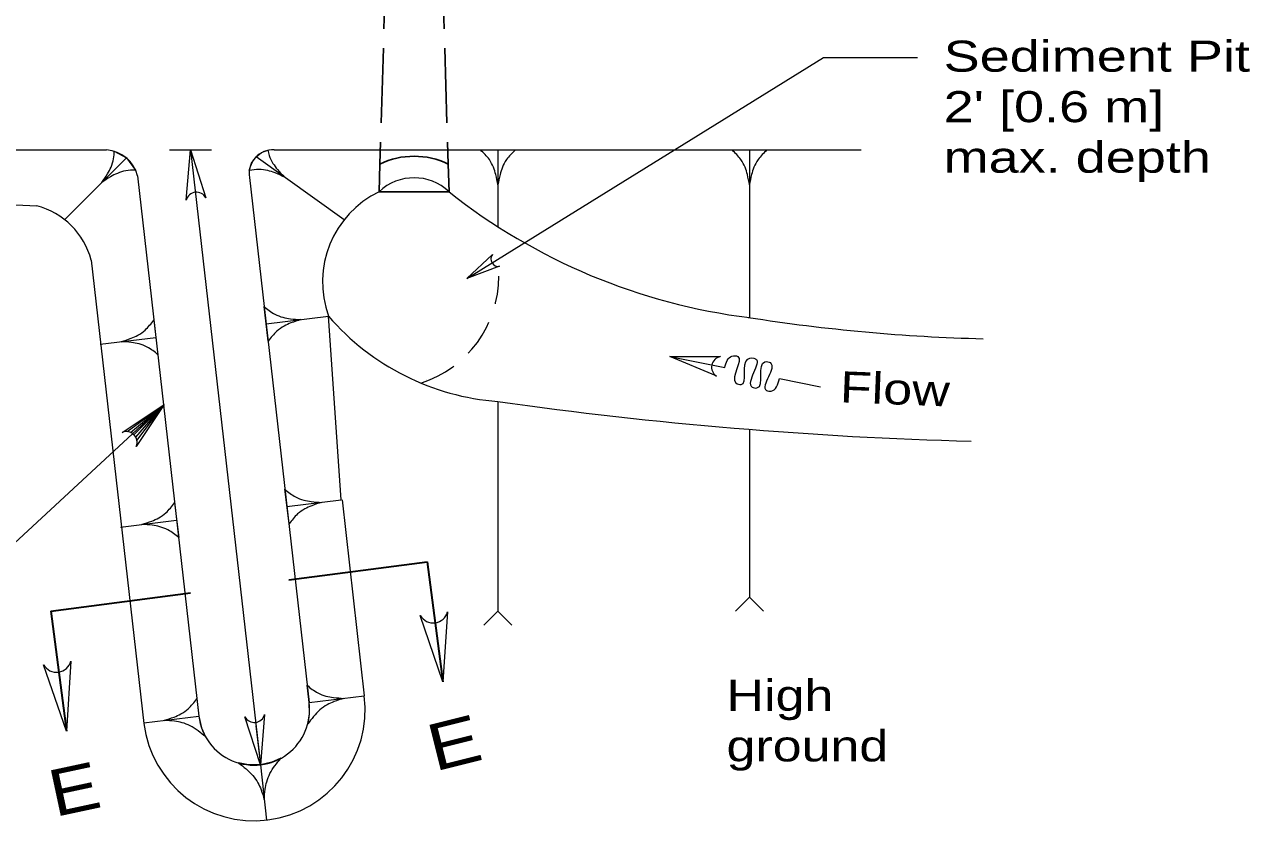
# Model space of a CAD drawing. Extents: x 1043.1 to 1101.1, y 672.4 to 716.4.
# Drawn here: x 1050.72 to 1057.03, y 684.13 to 688.26 of the extents above; entities that cross this region are included whole.
import ezdxf
from ezdxf.enums import TextEntityAlignment as Align

# ---------------------------------------------------------------- set-up
doc = ezdxf.new("R2010")
doc.units = 0
doc.header["$LTSCALE"] = 0.064
doc.linetypes.add('LONG_DASHED', pattern=[7.5, 6, -1.5])
doc.linetypes.add('MEDIUM_DASHED', pattern=[4.5, 3, -1.5])
doc.layers.add('1', color=7, linetype='Continuous', lineweight=13)

msp = doc.modelspace()

# ---------------------------------------------------------------- linework, layer by layer
at = {"layer": '1', "linetype": 'LONG_DASHED', "lineweight": 25}
for p, q in [((1052.58533, 688.62467), (1052.55375, 687.54417)), ((1052.87325, 688.62467), (1052.905, 687.54417))]:
    msp.add_line(p, q, dxfattribs=at)
at = {"layer": '1'}
for p, q in [((1047.11617, 687.61725), (1051.14617, 687.61725)), ((1051.24892, 687.57625), (1050.92983, 687.25717)), ((1051.46992, 687.61725), (1051.68583, 687.61725)), ((1052.3695, 687.2575), (1051.916, 687.58142)), ((1052.00975, 687.61725), (1055.03217, 687.61725)), ((1053.07117, 687.61725), (1053.25117, 687.61725)), ((1053.07117, 687.61725), (1053.25117, 687.61725)), ((1053.16117, 687.61725), (1053.16117, 687.2215)), ((1054.3665, 687.61725), (1054.54642, 687.61725)), ((1054.4565, 687.61725), (1054.4565, 686.75392)), ((1051.30533, 687.48342), (1051.62133, 684.702)), ((1051.88192, 687.47517), (1052.18917, 684.77167)), ((1051.06675, 687.049), (1051.33783, 684.66425)), ((1051.9785, 686.63208), (1051.95675, 686.81067)), ((1051.9785, 686.63208), (1051.95675, 686.81067)), ((1051.38883, 686.74092), (1051.41075, 686.5625)), ((1051.96767, 686.72142), (1052.28892, 686.76092)), ((1052.354, 685.81492), (1052.28892, 686.76092)), ((1051.11233, 686.61642), (1051.39975, 686.65167)), ((1054.0465, 686.553), (1054.32875, 686.49625)), ((1054.61092, 686.43942), (1054.82267, 686.39692)), ((1051.25233, 686.16692), (1051.44233, 686.307)), ((1051.26917, 686.1625), (1051.44233, 686.307)), ((1051.28675, 686.15075), (1051.44233, 686.307)), ((1051.2965, 686.13758), (1051.44233, 686.307)), ((1051.30233, 686.12075), (1051.44233, 686.307)), ((1053.16117, 686.32208), (1053.16117, 685.24267)), ((1054.4565, 686.17825), (1054.4565, 685.31467)), ((1052.08542, 685.69125), (1052.06367, 685.86967)), ((1051.49575, 685.80008), (1051.51767, 685.62158)), ((1052.0745, 685.78058), (1052.354, 685.81492)), ((1052.35842, 685.81542), (1052.473, 684.8065)), ((1051.21842, 685.6755), (1051.50675, 685.71092)), ((1053.16117, 685.24267), (1053.08917, 685.17092)), ((1053.16117, 685.24267), (1053.23317, 685.17092)), ((1052.18917, 684.77167), (1052.473, 684.8065)), ((1051.3375, 684.66708), (1051.62133, 684.702)), ((1051.91492, 684.65217), (1051.93775, 684.45117))]:
    msp.add_line(p, q, dxfattribs=at)
at = {"layer": '1', "lineweight": 25}
for p, q in [((1052.5495, 687.4015), (1052.55375, 687.54417)), ((1052.90925, 687.4015), (1052.905, 687.54417)), ((1052.5495, 687.4015), (1052.90925, 687.4015)), ((1054.4565, 685.31467), (1054.3845, 685.24267)), ((1054.4565, 685.31467), (1054.52842, 685.24267))]:
    msp.add_line(p, q, dxfattribs=at)
at = {"layer": '1', "lineweight": 35}
for p, q in [((1052.08475, 685.40317), (1052.79642, 685.49617)), ((1052.79642, 685.49617), (1052.87725, 684.87842)), ((1050.85833, 685.24267), (1051.57775, 685.33675)), ((1050.85833, 685.24267), (1050.93917, 684.625))]:
    msp.add_line(p, q, dxfattribs=at)
at = {"layer": '1'}
for points in [[(1053.00092, 686.95475), (1054.83842, 688.09183), (1055.32175, 688.09183)], [(1051.18533, 687.61), (1051.24875, 687.57625), (1051.29433, 687.51267)], [(1051.55617, 687.35892), (1051.57792, 687.61725), (1051.65717, 687.3705), (1051.65692, 687.3705)], [(1051.57792, 687.61725), (1051.93775, 684.45117), (1051.97, 684.16717)], [(1051.8805, 687.51025), (1051.89275, 687.5495), (1051.91567, 687.582), (1051.94417, 687.6035), (1051.97692, 687.61492)], [(1047.11617, 687.3295), (1049.275, 687.4015), (1050.78633, 687.3295)], [(1053.16958, 687.01767), (1053.00092, 686.95475), (1053.13242, 687.07767), (1053.13242, 687.07758)], [(1054.28575, 686.45308), (1054.0465, 686.553), (1054.30583, 686.55275), (1054.30583, 686.5525)], [(1051.44233, 686.307), (1049.68783, 684.68225), (1049.16592, 684.68225)], [(1051.22633, 686.16242), (1051.44233, 686.307), (1051.29867, 686.0905)], [(1052.90175, 685.23858), (1052.87725, 684.87842), (1052.76142, 685.22033), (1052.7615, 685.22025)], [(1050.96208, 684.98525), (1050.93917, 684.625), (1050.82183, 684.96642), (1050.82192, 684.96633)], [(1052.18192, 684.66158), (1052.19075, 684.7145), (1052.18925, 684.77142), (1052.17825, 684.86092)], [(1051.61025, 684.79125), (1051.62117, 684.702), (1051.63417, 684.642), (1051.65575, 684.59508)], [(1051.9595, 684.70958), (1051.93775, 684.45117), (1051.8585, 684.69817), (1051.85867, 684.69817)], [(1052.0435, 684.48492), (1051.99767, 684.465), (1051.93883, 684.45125), (1051.87642, 684.45067), (1051.82533, 684.46075)]]:
    msp.add_lwpolyline(points, dxfattribs=at)
for centre, radius, start, end in [((1051.60884, 687.34417), 0.05488, 28.57163, 164.39776), ((1053.16322, 687.05515), 0.03811, 143.83798, 279.6641), ((1054.31604, 686.49869), 0.05488, 100.72224, 236.54837), ((1051.248, 686.11185), 0.05501, 337.19963, 113.02576), ((1052.82795, 685.25788), 0.0764, 209.50449, 345.33062), ((1050.88819, 685.00424), 0.0764, 209.75778, 345.5839), ((1051.90682, 684.72442), 0.05488, 208.57163, 344.39776)]:
    msp.add_arc(centre, radius, start, end, dxfattribs=at)
for centre, major_axis, start_param, end_param in [((1051.13154, 687.43849), (0.17947, 0), 0.2528676, 1.4893571), ((1052.00303, 687.4949), (0.12264, 0), 1.5162862, 3.3026684), ((1052.72935, 687.21259), (-0.26087, 0), 3.9513762, 5.4734017), ((1052.77343, 686.93713), (-0.51559, 0), 5.1617951, 6.6322278), ((1054.83633, 689.83284), (-3.10264, 0), 0.9006444, 1.4480657), ((1050.68585, 686.94871), (0.39387, 0), 0.2574972, 1.3128716), ((1053.25603, 687.59696), (-1.27849, 0), 0.7129535, 1.4965093), ((1055.88909, 695.87482), (-9.23372, 0), 1.4142788, 1.5459847), ((1056.16614, 707.46378), (-21.35636, 0), 1.4296205, 1.5442012), ((1051.90542, 684.73547), (-0.57205, 0), 0.1246434, 3.2660493), ((1051.90542, 684.73542), (-0.28603, 0), 0.1170532, 3.2687764)]:
    msp.add_ellipse(centre, major_axis=major_axis, ratio=0.999895, start_param=start_param, end_param=end_param, dxfattribs=at)
at = {"layer": '1', "lineweight": 25}
for centre, major_axis, ratio, start_param, end_param in [((1052.72935, 687.18035), (-0.40408, 0), 0.999895, 4.2625178, 5.1622602), ((1052.83136, 686.96122), (0.56619, 0.11263), 0.904707, 4.4638988, 4.4648781)]:
    msp.add_ellipse(centre, major_axis=major_axis, ratio=ratio, start_param=start_param, end_param=end_param, dxfattribs=at)
at = {"layer": '1', "linetype": 'MEDIUM_DASHED'}
msp.add_ellipse((1052.59129, 686.96443), major_axis=(0.57422, 0), ratio=0.999895, start_param=5.0183817, end_param=6.2872017, dxfattribs=at)
at = {"layer": '1'}
for points in [[(1051.12167, 687.44892), (1051.151, 687.49358), (1051.169, 687.52867), (1051.18192, 687.57175), (1051.18533, 687.61008)], [(1051.97692, 687.61492), (1051.98275, 687.588), (1052.00267, 687.54767), (1052.02617, 687.516), (1052.0625, 687.47675)], [(1053.16117, 687.43742), (1053.15033, 687.48967), (1053.13825, 687.52725), (1053.11692, 687.56692), (1053.07117, 687.61725)], [(1053.16117, 687.43742), (1053.15033, 687.48967), (1053.13825, 687.52725), (1053.11692, 687.56692), (1053.07117, 687.61725)], [(1053.25117, 687.61725), (1053.20533, 687.56692), (1053.184, 687.52725), (1053.17192, 687.48967), (1053.16117, 687.43742)], [(1053.25117, 687.61725), (1053.20533, 687.56692), (1053.184, 687.52725), (1053.17192, 687.48967), (1053.16117, 687.43742)], [(1054.4565, 687.43742), (1054.44575, 687.48967), (1054.43367, 687.52725), (1054.41233, 687.56692), (1054.3665, 687.61725)], [(1054.54642, 687.61725), (1054.50075, 687.56692), (1054.47942, 687.52725), (1054.46733, 687.48967), (1054.4565, 687.43742)], [(1051.29433, 687.51267), (1051.2445, 687.50925), (1051.20142, 687.49625), (1051.16625, 687.47825), (1051.12167, 687.44892)], [(1052.0625, 687.47675), (1052.01375, 687.49842), (1051.976, 687.51042), (1051.9315, 687.51608), (1051.8805, 687.51025)], [(1051.95675, 686.81067), (1052.01233, 686.77142), (1052.05425, 686.75508), (1052.093, 686.74767), (1052.14617, 686.74325)], [(1051.95675, 686.81067), (1052.01233, 686.77142), (1052.05425, 686.75508), (1052.093, 686.74767), (1052.14617, 686.74325)], [(1051.22125, 686.62967), (1051.27183, 686.64692), (1051.30767, 686.66342), (1051.34433, 686.68925), (1051.38883, 686.74092)], [(1052.14617, 686.74325), (1052.0955, 686.72617), (1052.05992, 686.70958), (1052.02317, 686.68367), (1051.9785, 686.63208)], [(1052.14617, 686.74325), (1052.0955, 686.72617), (1052.05992, 686.70958), (1052.02317, 686.68367), (1051.9785, 686.63208)], [(1051.41075, 686.5625), (1051.35517, 686.60167), (1051.31325, 686.61808), (1051.2745, 686.6255), (1051.22125, 686.62967)], [(1054.32875, 686.49625), (1054.36583, 686.55575), (1054.396, 686.55367), (1054.387, 686.41725), (1054.4135, 686.40875), (1054.44825, 686.54008), (1054.48783, 686.542), (1054.47083, 686.39558), (1054.49492, 686.39158), (1054.53625, 686.5265), (1054.5635, 686.52167), (1054.544, 686.37908), (1054.568, 686.37525), (1054.61092, 686.43942)], [(1052.06367, 685.86967), (1052.11917, 685.8305), (1052.161, 685.81425), (1052.19983, 685.80692), (1052.25317, 685.8025)], [(1051.32817, 685.68892), (1051.37867, 685.70608), (1051.41442, 685.72258), (1051.45117, 685.7485), (1051.49575, 685.80008)], [(1052.25317, 685.8025), (1052.20242, 685.78542), (1052.16675, 685.76875), (1052.12992, 685.74292), (1052.08542, 685.69125)], [(1051.51767, 685.62158), (1051.46192, 685.66075), (1051.42, 685.67708), (1051.38133, 685.68458), (1051.32817, 685.68892)], [(1052.17825, 684.86092), (1052.23392, 684.82167), (1052.27575, 684.8055), (1052.3145, 684.798), (1052.36775, 684.79358)], [(1051.44275, 684.68008), (1051.49333, 684.69708), (1051.52917, 684.71375), (1051.56583, 684.73967), (1051.61025, 684.79125)], [(1052.36775, 684.79358), (1052.31717, 684.7765), (1052.28142, 684.76), (1052.24475, 684.73408), (1052.18192, 684.66158)], [(1051.65633, 684.59458), (1051.57667, 684.652), (1051.53475, 684.66825), (1051.496, 684.67567), (1051.44275, 684.68008)], [(1051.958, 684.2725), (1051.96283, 684.32567), (1051.97075, 684.36425), (1051.98733, 684.40608), (1052.0435, 684.48492)], [(1051.82533, 684.46075), (1051.8995, 684.39608), (1051.92517, 684.35917), (1051.94142, 684.32325), (1051.958, 684.2725)]]:
    msp.add_spline(points, degree=3, dxfattribs=at)

# ---------------------------------------------------------------- texts
for s, width, p in [('Sediment Pit', 1.3, (1055.45633, 688.01958)), ("2' [0.6 m]", 1.3, (1055.45633, 687.75958)), ('max. depth', 1.3, (1055.45633, 687.49958)), ('High', 1.25, (1054.33825, 684.72892)), ('ground', 1.25, (1054.33825, 684.46892))]:
    msp.add_text(s, height=0.16, dxfattribs=dict(at, width=width)).set_placement(p)
at = {"layer": '1', "width": 1.25}
msp.add_text('Flow', height=0.16, rotation=357.755, dxfattribs=at).set_placement((1054.92025, 686.31783))
at = {"layer": '1'}
for rotation, width, p in [(14.035, 1.25, (1052.9649, 684.44847)), (12.094, 1.2, (1051.00469, 684.20883))]:
    msp.add_text('E', height=0.24, rotation=rotation, dxfattribs=dict(at, width=width)).set_placement(p, align=Align.CENTER)

doc.saveas('drawing.dxf')
